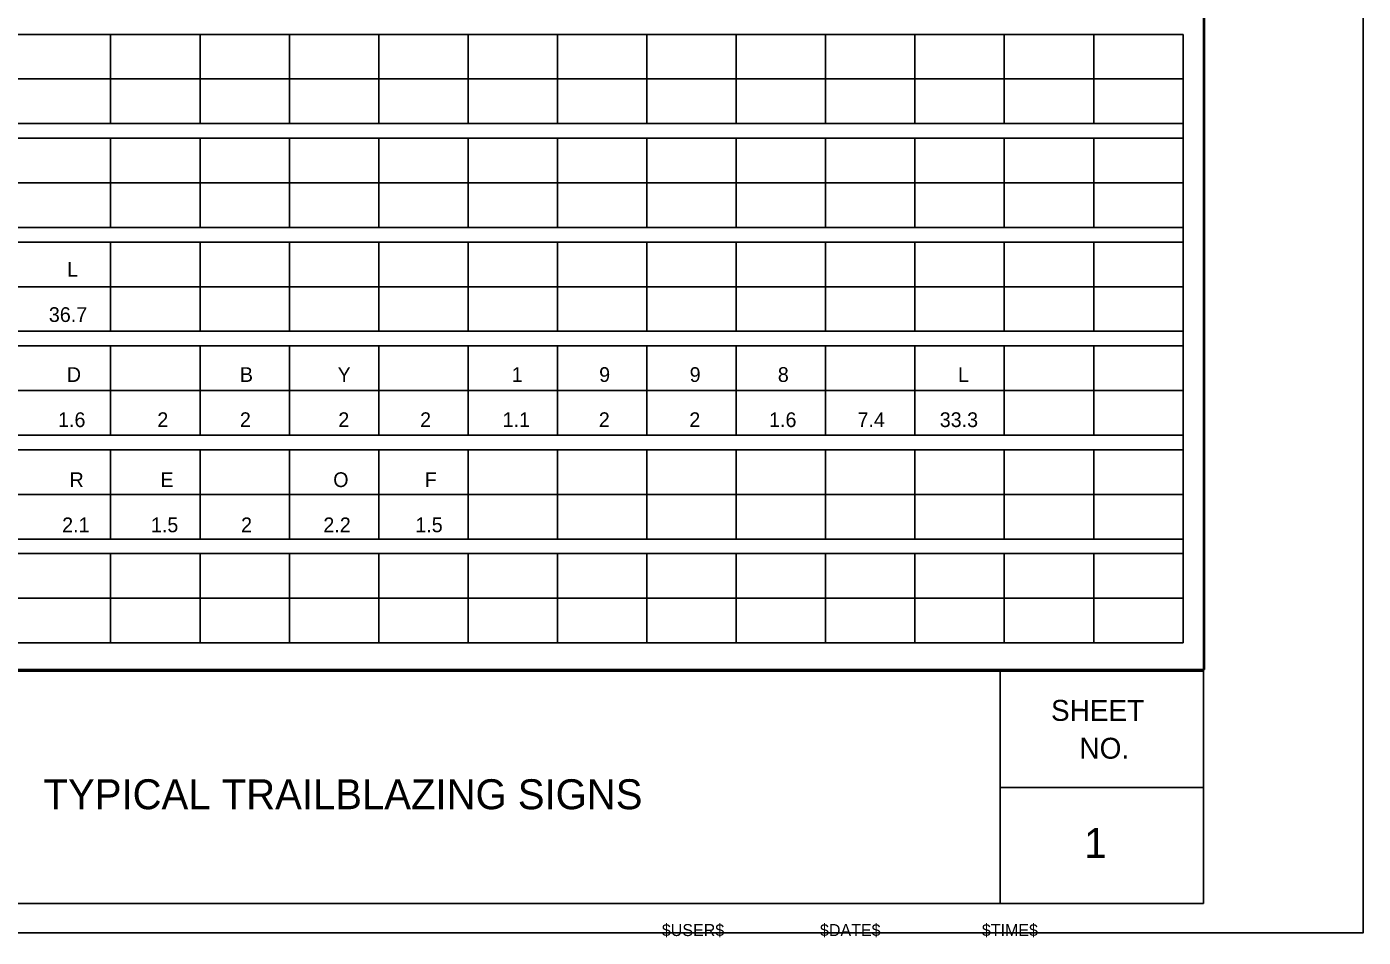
# Model space of a CAD drawing. Extents: x 17890628 to 17890844, y 17897693 to 17898031.
# Drawn here: x 17890803.98 to 17890843.99, y 17897907.47 to 17897934.73 of the extents above; entities that cross this region are included whole.
import ezdxf

# ---------------------------------------------------------------- set-up
doc = ezdxf.new("R2010")
doc.units = 0
for name, color, linetype in [('GSSign', 7, 'Continuous'), ('PlotBorder_dp', 7, 'Continuous'), ('SheetBorder_dp', 7, 'Continuous'), ('SheetLines_dp', 7, 'Continuous'), ('SheetLinesMisc2_dp', 7, 'Continuous'), ('TextMisc', 7, 'Continuous')]:
    doc.layers.add(name, color=color, linetype=linetype)

msp = doc.modelspace()

# ---------------------------------------------------------------- linework, layer by layer
at = {"layer": 'PlotBorder_dp'}
msp.add_lwpolyline([(17890700.471, 17897907.61), (17890843.989, 17897907.61), (17890843.989, 17897999.809), (17890700.471, 17897999.809)], close=True, dxfattribs=at)
at = {"layer": 'SheetBorder_dp'}
for p, q in [((17890839.205, 17897998.94), (17890839.205, 17897908.479)), ((17890705.254, 17897915.438), (17890839.205, 17897915.438)), ((17890705.254, 17897908.479), (17890839.205, 17897908.479))]:
    msp.add_line(p, q, dxfattribs=at)
at = {"layer": 'SheetLines_dp'}
for p, q in [((17890833.116, 17897908.479), (17890833.116, 17897915.438)), ((17890833.116, 17897911.959), (17890839.205, 17897911.959))]:
    msp.add_line(p, q, dxfattribs=at)
at = {"layer": 'SheetLinesMisc2_dp'}
for p, q in [((17890839.233, 17897915.484), (17890839.233, 17897998.731)), ((17890772.824, 17897934.497), (17890838.594, 17897934.497)), ((17890806.488, 17897934.497), (17890806.488, 17897931.825)), ((17890809.164, 17897934.497), (17890809.164, 17897931.825)), ((17890811.839, 17897934.497), (17890811.839, 17897931.825)), ((17890814.514, 17897934.497), (17890814.514, 17897931.825)), ((17890817.19, 17897934.497), (17890817.19, 17897931.825)), ((17890819.866, 17897934.497), (17890819.866, 17897931.825)), ((17890822.541, 17897934.497), (17890822.541, 17897931.825)), ((17890825.216, 17897934.497), (17890825.216, 17897931.825)), ((17890827.892, 17897934.497), (17890827.892, 17897931.825)), ((17890830.568, 17897934.497), (17890830.568, 17897931.825)), ((17890833.243, 17897934.497), (17890833.243, 17897931.825)), ((17890835.919, 17897934.497), (17890835.919, 17897931.825)), ((17890838.594, 17897916.286), (17890838.594, 17897934.497)), ((17890772.824, 17897933.162), (17890838.594, 17897933.162)), ((17890772.824, 17897931.825), (17890838.594, 17897931.825)), ((17890772.824, 17897931.389), (17890838.594, 17897931.389)), ((17890806.488, 17897931.389), (17890806.488, 17897928.717)), ((17890809.164, 17897931.389), (17890809.164, 17897928.717)), ((17890811.839, 17897931.389), (17890811.839, 17897928.717)), ((17890814.514, 17897931.389), (17890814.514, 17897928.717)), ((17890817.19, 17897931.389), (17890817.19, 17897928.717)), ((17890819.866, 17897931.389), (17890819.866, 17897928.717)), ((17890822.541, 17897931.389), (17890822.541, 17897928.717)), ((17890825.216, 17897931.389), (17890825.216, 17897928.717)), ((17890827.892, 17897931.389), (17890827.892, 17897928.717)), ((17890830.568, 17897931.389), (17890830.568, 17897928.717)), ((17890833.243, 17897931.389), (17890833.243, 17897928.717)), ((17890835.919, 17897931.389), (17890835.919, 17897928.717)), ((17890772.824, 17897930.053), (17890838.594, 17897930.053)), ((17890772.824, 17897928.717), (17890838.594, 17897928.717)), ((17890772.824, 17897928.281), (17890838.594, 17897928.281)), ((17890806.488, 17897928.281), (17890806.488, 17897925.609)), ((17890809.164, 17897928.281), (17890809.164, 17897925.609)), ((17890811.839, 17897928.281), (17890811.839, 17897925.609)), ((17890814.514, 17897928.281), (17890814.514, 17897925.609)), ((17890817.19, 17897928.281), (17890817.19, 17897925.609)), ((17890819.866, 17897928.281), (17890819.866, 17897925.609)), ((17890822.541, 17897928.281), (17890822.541, 17897925.609)), ((17890825.216, 17897928.281), (17890825.216, 17897925.609)), ((17890827.892, 17897928.281), (17890827.892, 17897925.609)), ((17890830.568, 17897928.281), (17890830.568, 17897925.609)), ((17890833.243, 17897928.281), (17890833.243, 17897925.609)), ((17890835.919, 17897928.281), (17890835.919, 17897925.609)), ((17890772.824, 17897926.945), (17890838.594, 17897926.945)), ((17890772.824, 17897925.609), (17890838.594, 17897925.609)), ((17890772.824, 17897925.173), (17890838.594, 17897925.173)), ((17890806.488, 17897925.173), (17890806.488, 17897922.501)), ((17890809.164, 17897925.173), (17890809.164, 17897922.501)), ((17890811.839, 17897925.173), (17890811.839, 17897922.501)), ((17890814.514, 17897925.173), (17890814.514, 17897922.501)), ((17890817.19, 17897925.173), (17890817.19, 17897922.501)), ((17890819.866, 17897925.173), (17890819.866, 17897922.501)), ((17890822.541, 17897925.173), (17890822.541, 17897922.501)), ((17890825.216, 17897925.173), (17890825.216, 17897922.501)), ((17890827.892, 17897925.173), (17890827.892, 17897922.501)), ((17890830.568, 17897925.173), (17890830.568, 17897922.501)), ((17890833.243, 17897925.173), (17890833.243, 17897922.501)), ((17890835.919, 17897925.173), (17890835.919, 17897922.501)), ((17890772.824, 17897923.838), (17890838.594, 17897923.838)), ((17890772.824, 17897922.501), (17890838.594, 17897922.501)), ((17890772.824, 17897922.065), (17890838.594, 17897922.065)), ((17890806.488, 17897922.065), (17890806.488, 17897919.393)), ((17890809.164, 17897922.065), (17890809.164, 17897919.393)), ((17890811.839, 17897922.065), (17890811.839, 17897919.393)), ((17890814.514, 17897922.065), (17890814.514, 17897919.393)), ((17890817.19, 17897922.065), (17890817.19, 17897919.393)), ((17890819.866, 17897922.065), (17890819.866, 17897919.393)), ((17890822.541, 17897922.065), (17890822.541, 17897919.393)), ((17890825.216, 17897922.065), (17890825.216, 17897919.393)), ((17890827.892, 17897922.065), (17890827.892, 17897919.393)), ((17890830.568, 17897922.065), (17890830.568, 17897919.393)), ((17890833.243, 17897922.065), (17890833.243, 17897919.393)), ((17890835.919, 17897922.065), (17890835.919, 17897919.393)), ((17890772.824, 17897920.729), (17890838.594, 17897920.729)), ((17890772.824, 17897919.393), (17890838.594, 17897919.393)), ((17890772.824, 17897918.958), (17890838.594, 17897918.958)), ((17890806.488, 17897918.958), (17890806.488, 17897916.286)), ((17890809.164, 17897918.958), (17890809.164, 17897916.286)), ((17890811.839, 17897918.958), (17890811.839, 17897916.286)), ((17890814.514, 17897918.958), (17890814.514, 17897916.286)), ((17890817.19, 17897918.958), (17890817.19, 17897916.286)), ((17890819.866, 17897918.958), (17890819.866, 17897916.286)), ((17890822.541, 17897918.958), (17890822.541, 17897916.286)), ((17890825.216, 17897918.958), (17890825.216, 17897916.286)), ((17890827.892, 17897918.958), (17890827.892, 17897916.286)), ((17890830.568, 17897918.958), (17890830.568, 17897916.286)), ((17890833.243, 17897918.958), (17890833.243, 17897916.286)), ((17890835.919, 17897918.958), (17890835.919, 17897916.286)), ((17890772.824, 17897917.622), (17890838.594, 17897917.622)), ((17890772.824, 17897916.286), (17890838.594, 17897916.286)), ((17890705.5, 17897915.484), (17890839.233, 17897915.484))]:
    msp.add_line(p, q, dxfattribs=at)

# ---------------------------------------------------------------- texts
at = {"layer": 'GSSign'}
for s, height, p in [('L', 0.441, (17890805.184, 17897927.242)), ('36.7', 0.4411, (17890804.638, 17897925.889)), ('D', 0.441, (17890805.175, 17897924.095)), ('B', 0.441, (17890810.357, 17897924.095)), ('Y', 0.441, (17890813.282, 17897924.095)), ('1', 0.441, (17890818.496, 17897924.095)), ('9', 0.441, (17890821.113, 17897924.095)), ('9', 0.441, (17890823.823, 17897924.095)), ('8', 0.441, (17890826.462, 17897924.095)), ('L', 0.441, (17890831.855, 17897924.095)), ('1.6', 0.4411, (17890804.913, 17897922.743)), ('2', 0.441, (17890807.885, 17897922.743)), ('2', 0.441, (17890810.357, 17897922.743)), ('2', 0.441, (17890813.303, 17897922.743)), ('2', 0.441, (17890815.752, 17897922.743)), ('1.1', 0.4411, (17890818.222, 17897922.743)), ('2', 0.441, (17890821.103, 17897922.743)), ('2', 0.441, (17890823.812, 17897922.743)), ('1.6', 0.4411, (17890826.2, 17897922.743)), ('7.4', 0.4411, (17890828.848, 17897922.743)), ('33.3', 0.4411, (17890831.309, 17897922.743)), ('R', 0.441, (17890805.257, 17897920.948)), ('E', 0.441, (17890807.977, 17897920.948)), ('O', 0.441, (17890813.151, 17897920.948)), ('F', 0.441, (17890815.891, 17897920.948)), ('2.1', 0.4411, (17890805.036, 17897919.596)), ('1.5', 0.4411, (17890807.693, 17897919.596)), ('2', 0.441, (17890810.393, 17897919.596)), ('2.2', 0.4411, (17890812.856, 17897919.596)), ('1.5', 0.4411, (17890815.608, 17897919.596))]:
    msp.add_text(s, height=height, dxfattribs=at).set_placement(p)
at = {"layer": 'TextMisc'}
for s, p in [('SHEET', (17890834.639, 17897913.951)), ('NO.', (17890835.491, 17897912.82))]:
    msp.add_text(s, height=0.6263, rotation=359.8607, dxfattribs=at).set_placement(p)
for s, height, p in [('TYPICAL TRAILBLAZING SIGNS', 0.89699, (17890804.48, 17897911.305)), ('1', 0.897, (17890835.636, 17897909.843)), ('$USER$', 0.3588, (17890822.99, 17897907.509)), ('$DATE$', 0.3588, (17890827.724, 17897907.509)), ('$TIME$', 0.3588, (17890832.57, 17897907.509))]:
    msp.add_text(s, height=height, dxfattribs=at).set_placement(p)

doc.saveas('drawing.dxf')
